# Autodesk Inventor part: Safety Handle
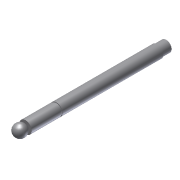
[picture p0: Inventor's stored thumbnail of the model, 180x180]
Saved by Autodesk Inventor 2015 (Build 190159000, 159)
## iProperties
Shininess: 77.0
Length Units: 11269
Angle Units: 11279
Time Units: 11290
Mass Units: 11283
Length Display Precision: 3
Angle Display Precision: 2
Created: 2002-02
Part Number: Safety Handle
Document SubType Name: Modeling
Designer: ***
Density: 1 g/cm^3
Material: Generic
Mass: 54.3914 g
Surface Area: 130.219 cm^2
Volume: 54.3914 cm^3
Appearance: Default
Density: 0.0
Volumn: 0.0
Area: 0.0
PropertySet Name: Model Information
Control State: 0
Master: False
Checked Out: False
Author: ***
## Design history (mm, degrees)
sketch "Sketch1"
  geometry: L1 (0, 205)-(8, 205); L2 (8, 205)-(8, 192); L3 (8, 192)-(9, 192); L4 (9, 192)-(9, 45); L5 (9, 45)-(8, 45); L6 (8, 45)-(8, 43); L7 (8, 43)-(9, 43); L8 (9, 43)-(9, 0); L9 (9, 0)-(0, 0); L10 (0, 0)-(0, 205)
  constraints: 20 end point, 7 parallel, 1 collinear, 1 horizontal, 1 perpendicular
  dimensions: "d0" = 13 distance of L1.end L2.end; "d1" = 2 distance of L4.end L7.end; "d2" = 43 distance of L7.end L8.end; "d3" = 205 distance of L9.end L1.start; "d4" = 16 diameter of L2 L10; "d5" = 18 diameter of L4 L10; "d6" = 16 diameter of L6.end L10
revolve "Revolution1" sketch "Sketch1" stored, may be unused: angle "d7" = 90 deg
sketch "Sketch2"
  geometry: L1 (0, 1)-(0, -17); L2 (-9, 0)-(9, 0) reference; A1 r 9 centre (0, -8) between (0, -17) and (0, 1)
  constraints: 2 end point, 2 point on circle, 1 centre point, 1 midpoint, 1 vertical
  dimensions: "d8" = 9 radius of A1; "d9" = 1 distance from line of L2 L1.start
revolve "Revolution2" sketch "Sketch2" stored, may be unused: angle "d10" = 90 deg
body "Solid1"
